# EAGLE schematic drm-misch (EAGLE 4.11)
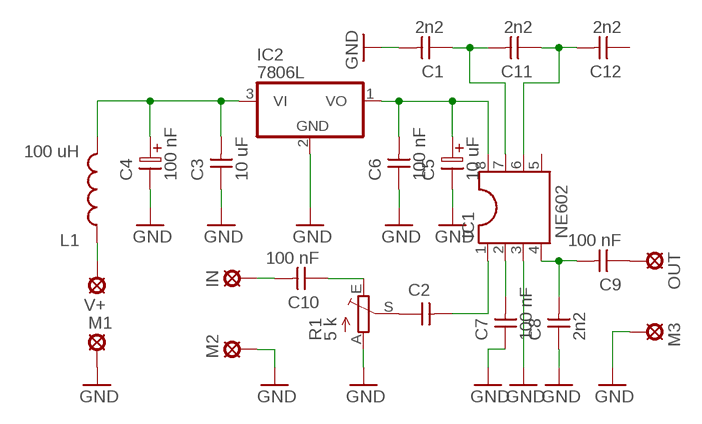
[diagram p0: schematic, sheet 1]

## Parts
C1  2n2  CAPNP-5  [C-5]
C2  CAPNP-5  [C-5]
C3  10 uF  CAPNP-5  [C-5]
C4  100 nF  ELC-5  [ES-5]
C5  10 uF  ELC-5  [ES-5]
C6  100 nF  CAPNP-5  [C-5]
C7  100 nF  CAPNP-5  [C-5]
C8  2n2  CAPNP-5  [C-5]
C9  100 nF  CAPNP-5  [C-5]
C10  100 nF  CAPNP-5  [C-5]
C11  2n2  CAPNP-5  [C-5]
C12  2n2  CAPNP-5  [C-5]
IC1  NE602  DIL8  [DIL08]
IC2  7806L  [TO92]
IN  MCS10B  [MCS10B]
L1  100 uH  L-12,5  [L-12,5]
M1  MCS10B  [MCS10B]
M2  MCS10B  [MCS10B]
M3  MCS10B  [MCS10B]
OUT  MCS10B  [MCS10B]
R1  5 k  TRIM_EU-LI10  [LI10]
V+  MCS10B  [MCS10B]

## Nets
GND: C1.2 C3.1 C4.2 C5.2 C6.1 C7.1 C8.1 IC1.3 IC2.2(GND) M1.MP M2.MP M3.MP R1.A
N$1: C2.2 IC1.1
N$2: C2.1 R1.S
N$3: C5.1 C6.2 IC1.8 IC2.1(VO)
N$4: C3.2 C4.1 IC2.3(VI) L1.2
N$5: C7.2 IC1.2
N$6: C10.1 R1.E
N$7: C8.2 C9.2 IC1.4
N$8: C1.1 C11.2 IC1.7
N$9: C11.1 C12.2 IC1.6
N$10: L1.1 V+.MP
N$11: C10.2 IN.MP
N$12: C9.1 OUT.MP
Unconnected: C12.1 IC1.5

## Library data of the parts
C1-C3 C6-C12 = discrete:CAPNP-5
C4 C5 = discrete:ELC-5
IC1 = ic-package:DIL8: Dual In Line
IC2 = linear:78*: Positive VOLTAGE REGULATOR
IN M1-M3 OUT V+ = solpad:MCS10B: SOLDER PAD
L1 = discrete:L-12,5
R1 = pot:TRIM_EU-: POTENTIOMETER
